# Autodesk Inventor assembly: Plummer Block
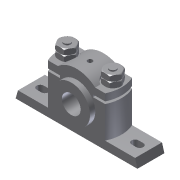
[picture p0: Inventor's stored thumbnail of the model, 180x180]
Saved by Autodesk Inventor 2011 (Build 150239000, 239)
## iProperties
Created: 2009-04
Part Number: Plummer Block
Document SubType Name: Assembly
Designer: Sham
Author: Sham
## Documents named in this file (7)
- C:\Users\CADSoft\Desktop\part files\c09-inv-2011-prt\Plummer Block\Plummer Block.iam
- C:\Inventor_2011\c09_inv_2011_02062010\Plummer Block\Casting1.ipt
- C:\Users\CADSoft\Desktop\part files\c09-inv-2011-prt\Plummer Block\Cap.ipt
- C:\Users\CADSoft\Desktop\part files\c09-inv-2011-prt\Plummer Block\Brasses.ipt
- C:\Users\CADSoft\Desktop\part files\c09-inv-2011-prt\Plummer Block\Bolt.ipt
- C:\Users\CADSoft\Desktop\part files\c09-inv-2011-prt\Plummer Block\Nut.ipt
- C:\Users\CADSoft\Desktop\part files\c09-inv-2011-prt\Plummer Block\Lock Nut.ipt
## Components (9 placed, 6 different names)
1. Casting:1 — Insert:1, Flush:1, Insert:2, Mate:1, Insert:3, Insert:4
2. Cap:1 — Insert:1, Flush:1, Insert:5, Insert:6
3. Brasses:1 — Insert:2, Mate:1
4. Bolt:1 — Insert:3
5. Bolt:2 — Insert:4
6. Nut:1 — Insert:6, Insert:7
7. Nut:2 — Insert:5, Insert:8
8. Lock Nut:1 — Insert:7
9. Lock Nut:2 — Insert:8
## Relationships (10: Insert 8, Flush 1, Mate 1)
- Insert:1: Casting:1 ↔ Cap:1
- Flush:1: Casting:1 ↔ Cap:1
- Insert:2: Casting:1 ↔ Brasses:1
- Mate:1: Casting:1 ↔ Brasses:1
- Insert:3: Casting:1 ↔ Bolt:1
- Insert:4: Casting:1 ↔ Bolt:2
- Insert:5: Cap:1 ↔ Nut:2
- Insert:6: Cap:1 ↔ Nut:1
- Insert:7: Nut:1 ↔ Lock Nut:1
- Insert:8: Nut:2 ↔ Lock Nut:2
